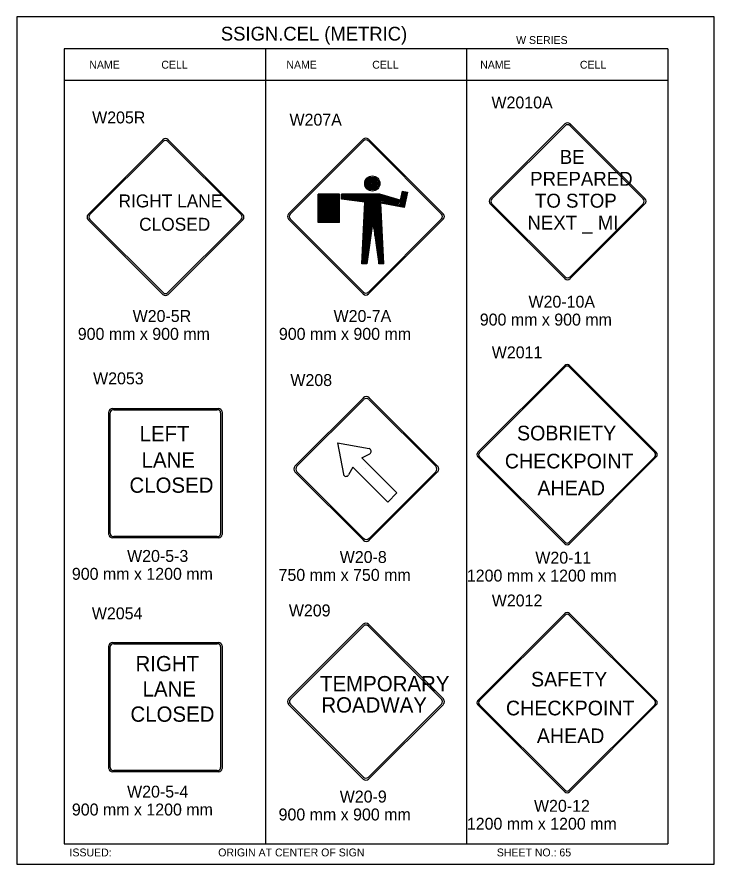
# Model space of a CAD drawing. Extents: x -12 to 6962, y -3756 to 679.
# Drawn here: x 2167.2 to 2342.4, y -696.1 to -483 of the extents above; entities that cross this region are included whole.
import ezdxf

# ---------------------------------------------------------------- set-up
doc = ezdxf.new("R2010")
doc.units = 0
for name, color, linetype in [('Level 1', 7, 'Continuous'), ('Level 2', 7, 'Continuous'), ('Level 3', 7, 'Continuous'), ('Level 62', 7, 'Continuous')]:
    doc.layers.add(name, color=color, linetype=linetype)

msp = doc.modelspace()

# ---------------------------------------------------------------- linework, layer by layer
at = {"layer": 'Level 1'}
for p, q in [((2330.8, -491.06), (2179.04, -491.06)), ((2179.04, -491.06), (2179.04, -691.06)), ((2229.63, -491.06), (2229.63, -691.06)), ((2280.21, -491.17), (2280.21, -691.17)), ((2330.8, -491.06), (2330.8, -691.06)), ((2330.8, -498.98), (2179.04, -498.98)), ((2286.15, -528.71), (2304.93, -509.93)), ((2286.6, -528.77), (2304.99, -510.38)), ((2306.22, -510.38), (2324.61, -528.77)), ((2306.27, -509.93), (2325.05, -528.71)), ((2185.06, -532.69), (2203.84, -513.91)), ((2185.51, -532.74), (2203.9, -514.35)), ((2205.13, -514.35), (2223.52, -532.74)), ((2205.19, -513.91), (2223.97, -532.69)), ((2235.44, -532.55), (2254.22, -513.77)), ((2235.88, -532.61), (2254.28, -514.21)), ((2255.51, -514.21), (2273.9, -532.61)), ((2255.56, -513.77), (2274.35, -532.55)), ((2242.92, -534.68), (2242.92, -527.57)), ((2248.26, -527.57), (2242.92, -527.57)), ((2243.18, -534.68), (2243.18, -527.57)), ((2243.43, -534.68), (2243.43, -527.57)), ((2243.68, -534.68), (2243.68, -527.57)), ((2243.94, -534.68), (2243.94, -527.57)), ((2244.19, -534.68), (2244.19, -527.57)), ((2244.45, -534.68), (2244.45, -527.57)), ((2244.7, -534.68), (2244.7, -527.57)), ((2244.95, -534.68), (2244.95, -527.57)), ((2245.21, -534.68), (2245.21, -527.57)), ((2245.46, -534.68), (2245.46, -527.57)), ((2245.72, -534.68), (2245.72, -527.57)), ((2245.97, -534.68), (2245.97, -527.57)), ((2246.22, -534.68), (2246.22, -527.57)), ((2246.48, -534.68), (2246.48, -527.57)), ((2246.73, -534.68), (2246.73, -527.57)), ((2246.99, -534.68), (2246.99, -527.57)), ((2247.24, -534.68), (2247.24, -527.57)), ((2247.49, -534.68), (2247.49, -527.57)), ((2247.75, -534.68), (2247.75, -527.57)), ((2248, -534.68), (2248, -527.57)), ((2248.26, -534.68), (2248.26, -527.57)), ((2258.42, -527.57), (2248.76, -527.57)), ((2248.76, -528.84), (2248.76, -527.57)), ((2258.42, -527.83), (2248.76, -527.83)), ((2258.42, -528.08), (2248.76, -528.08)), ((2258.42, -528.33), (2248.76, -528.33)), ((2254.67, -529.1), (2248.83, -528.34)), ((2254.7, -528.85), (2248.86, -528.09)), ((2263.28, -529.83), (2258.2, -528.3)), ((2263.35, -529.58), (2258.27, -528.06)), ((2263.42, -529.34), (2258.34, -527.82)), ((2263.5, -529.1), (2258.42, -527.57)), ((2264.11, -526.83), (2263.26, -530.65)), ((2264, -526.81), (2263.5, -529.1)), ((2264.36, -526.89), (2263.51, -530.71)), ((2264.6, -526.94), (2263.76, -530.76)), ((2264, -526.81), (2265.35, -527.11)), ((2264.85, -527), (2264, -530.82)), ((2265.1, -527.05), (2264.25, -530.87)), ((2265.35, -527.11), (2264.5, -530.93)), ((2258.42, -528.59), (2248.76, -528.59)), ((2254.61, -529.6), (2248.76, -528.84)), ((2254.64, -529.35), (2248.8, -528.59)), ((2253.84, -545.1), (2254.61, -529.6)), ((2254.1, -545.11), (2254.86, -529.62)), ((2254.35, -545.12), (2255.11, -529.63)), ((2254.61, -545.14), (2255.37, -529.64)), ((2254.86, -530.11), (2254.86, -528.59)), ((2254.86, -545.15), (2255.62, -529.65)), ((2255.11, -530.11), (2255.11, -528.59)), ((2255.11, -545.16), (2255.87, -529.67)), ((2255.37, -530.11), (2255.37, -528.59)), ((2255.56, -541.28), (2256.13, -529.68)), ((2255.62, -530.11), (2255.62, -528.59)), ((2255.88, -530.11), (2255.88, -528.59)), ((2255.88, -537.99), (2255.88, -530.11)), ((2256.13, -537.99), (2256.13, -528.59)), ((2256.38, -536.46), (2256.38, -528.59)), ((2256.64, -535.45), (2256.64, -528.59)), ((2256.89, -536.21), (2256.89, -528.59)), ((2257.15, -537.99), (2257.15, -528.59)), ((2257.69, -541.03), (2257.15, -529.93)), ((2257.4, -530.11), (2257.4, -528.59)), ((2258.15, -545.16), (2257.4, -529.92)), ((2257.4, -537.99), (2257.4, -530.11)), ((2257.65, -530.11), (2257.65, -528.59)), ((2258.41, -545.15), (2257.66, -529.91)), ((2257.91, -530.11), (2257.91, -528.59)), ((2258.66, -545.14), (2257.91, -529.9)), ((2263.06, -530.56), (2257.98, -529.03)), ((2263.13, -530.31), (2258.05, -528.79)), ((2263.2, -530.07), (2258.12, -528.55)), ((2258.16, -530.11), (2258.16, -528.59)), ((2258.91, -545.12), (2258.16, -529.88)), ((2258.42, -530.11), (2258.42, -528.59)), ((2259.17, -545.11), (2258.42, -529.87)), ((2258.67, -530.11), (2258.67, -528.59)), ((2264.5, -530.93), (2258.67, -529.86)), ((2259.42, -545.1), (2258.67, -529.86)), ((2264.55, -530.68), (2258.72, -529.61)), ((2304.93, -548.83), (2286.15, -530.05)), ((2304.99, -548.38), (2286.6, -530)), ((2305.64, -529.4), (2305.64, -529.4)), ((2324.61, -530), (2306.22, -548.38)), ((2325.05, -530.05), (2306.27, -548.83)), ((2203.84, -552.81), (2185.06, -534.03)), ((2203.9, -552.36), (2185.51, -533.97)), ((2204.5, -533.34), (2204.5, -533.34)), ((2223.52, -533.97), (2205.13, -552.36)), ((2223.97, -534.03), (2205.19, -552.81)), ((2254.22, -552.68), (2235.44, -533.89)), ((2254.28, -552.23), (2235.88, -533.84)), ((2248.26, -534.68), (2242.92, -534.68)), ((2254.95, -533.25), (2254.95, -533.25)), ((2256.63, -534.47), (2255.11, -545.1)), ((2273.9, -533.84), (2255.51, -552.23)), ((2274.35, -533.89), (2255.56, -552.68)), ((2256.63, -534.47), (2258.15, -545.1)), ((2255.88, -537.88), (2254.87, -544.99)), ((2257.38, -537.88), (2258.4, -544.99)), ((2255.11, -545.1), (2253.84, -545.1)), ((2259.42, -545.1), (2258.15, -545.1)), ((2283.06, -592.52), (2304.91, -570.67)), ((2283.44, -592.57), (2304.96, -571.06)), ((2306.01, -571.06), (2327.53, -592.57)), ((2306.06, -570.67), (2327.91, -592.52)), ((2237.06, -595.98), (2254.26, -578.79)), ((2237.56, -596.04), (2254.32, -579.29)), ((2255.69, -579.29), (2272.45, -596.04)), ((2255.75, -578.79), (2272.94, -595.98)), ((2191.21, -581.51), (2217.78, -581.51)), ((2190.26, -613.22), (2190.26, -582.32)), ((2190.62, -612.98), (2190.62, -582.56)), ((2191.49, -581.81), (2217.5, -581.81)), ((2218.37, -582.56), (2218.37, -612.98)), ((2218.73, -582.32), (2218.73, -613.22)), ((2247.79, -590.14), (2249.23, -598.04)), ((2247.79, -590.14), (2255.69, -591.58)), ((2253.9, -593.94), (2255.86, -592.9)), ((2253.9, -593.94), (2262.71, -602.76)), ((2304.91, -615.52), (2283.06, -593.67)), ((2304.96, -615.14), (2283.44, -593.63)), ((2305.49, -593.1), (2305.49, -593.1)), ((2327.53, -593.63), (2306.01, -615.14)), ((2327.91, -593.67), (2306.06, -615.52)), ((2251.6, -596.24), (2250.55, -598.21)), ((2260.41, -605.06), (2251.6, -596.24)), ((2254.77, -596.56), (2254.77, -596.56)), ((2204.48, -597.74), (2204.48, -597.74)), ((2254.26, -614.67), (2237.06, -597.48)), ((2254.32, -614.17), (2237.56, -597.41)), ((2272.45, -597.41), (2255.69, -614.17)), ((2272.94, -597.48), (2255.75, -614.67)), ((2262.71, -602.76), (2260.41, -605.06)), ((2217.78, -614.03), (2191.21, -614.03)), ((2217.5, -613.73), (2191.49, -613.73)), ((2283.06, -654.94), (2304.91, -633.09)), ((2283.44, -654.99), (2304.96, -633.47)), ((2306.01, -633.47), (2327.53, -654.99)), ((2306.06, -633.09), (2327.91, -654.94)), ((2235.45, -654.58), (2254.24, -635.8)), ((2235.9, -654.64), (2254.3, -636.25)), ((2255.53, -636.25), (2273.92, -654.64)), ((2255.58, -635.8), (2274.37, -654.58)), ((2190.26, -672.09), (2190.26, -641.19)), ((2191.21, -640.37), (2217.78, -640.37)), ((2191.49, -640.68), (2217.5, -640.68)), ((2218.73, -641.19), (2218.73, -672.09)), ((2190.62, -671.85), (2190.62, -641.42)), ((2218.37, -641.42), (2218.37, -671.85)), ((2254.24, -674.71), (2235.45, -655.93)), ((2254.3, -674.26), (2235.9, -655.87)), ((2254.81, -655.28), (2254.81, -655.28)), ((2273.92, -655.87), (2255.53, -674.26)), ((2274.37, -655.93), (2255.58, -674.71)), ((2304.91, -677.94), (2283.06, -656.09)), ((2304.96, -677.55), (2283.44, -656.04)), ((2305.49, -655.51), (2305.49, -655.51)), ((2327.53, -656.04), (2306.01, -677.55)), ((2327.91, -656.09), (2306.06, -677.94)), ((2204.4, -656.63), (2204.4, -656.63)), ((2217.78, -672.9), (2191.21, -672.9)), ((2217.5, -672.6), (2191.49, -672.6)), ((2179.04, -691.06), (2330.8, -691.06))]:
    msp.add_line(p, q, dxfattribs=at)
for centre, radius in [((2256.51, -524.91), 1.91), ((2256.49, -524.92), 1.62), ((2256.48, -524.94), 1.38), ((2256.46, -524.95), 1.17), ((2256.45, -524.97), 0.997), ((2256.48, -524.98), 0.847), ((2256.5, -524.98), 0.72), ((2256.52, -524.99), 0.612), ((2256.56, -525), 0.442), ((2256.6, -525.02), 0.204), ((2256.62, -525.03), 0.115)]:
    msp.add_circle(centre, radius, dxfattribs=at)
for centre, radius, start, end in [((2305.6, -510.6), 0.949, 45, 135), ((2305.6, -510.99), 0.87, 45, 135), ((2254.89, -514.44), 0.949, 45, 135), ((2204.52, -514.58), 0.949, 45, 135), ((2204.52, -514.97), 0.87, 45, 135), ((2254.89, -514.83), 0.87, 45, 135), ((2286.82, -529.38), 0.949, 135, 225), ((2287.21, -529.38), 0.87, 135, 225), ((2323.99, -529.38), 0.87, 315, 45), ((2324.38, -529.38), 0.949, 315, 45), ((2185.73, -533.36), 0.949, 135, 225), ((2223.3, -533.36), 0.949, 315, 45), ((2236.11, -533.22), 0.949, 135, 225), ((2236.5, -533.22), 0.87, 135, 225), ((2273.29, -533.22), 0.87, 315, 45), ((2273.68, -533.22), 0.949, 315, 45), ((2186.13, -533.36), 0.87, 135, 225), ((2222.9, -533.36), 0.87, 315, 45), ((2305.6, -548.16), 0.949, 225, 315), ((2305.6, -547.77), 0.87, 225, 315), ((2204.52, -552.14), 0.949, 225, 315), ((2204.52, -551.75), 0.87, 225, 315), ((2254.89, -552.01), 0.949, 225, 315), ((2254.89, -551.62), 0.87, 225, 315), ((2305.49, -571.25), 0.813, 45, 135), ((2305.49, -571.58), 0.745, 45, 135), ((2255, -579.54), 1.06, 45, 135), ((2255, -579.97), 0.969, 45, 135), ((2255.52, -592.27), 0.718, 298.6264, 76.9676), ((2283.64, -593.1), 0.813, 135, 225), ((2283.97, -593.1), 0.745, 135, 225), ((2327, -593.1), 0.745, 315, 45), ((2327.34, -593.1), 0.813, 315, 45), ((2237.81, -596.73), 1.06, 135, 225), ((2238.25, -596.73), 0.969, 135, 225), ((2271.76, -596.73), 0.969, 315, 45), ((2272.2, -596.73), 1.06, 315, 45), ((2249.92, -597.87), 0.712, 192.6656, 332.1451), ((2255, -613.92), 1.06, 225, 315), ((2255, -613.48), 0.969, 225, 315), ((2305.49, -614.95), 0.813, 225, 315), ((2305.49, -614.61), 0.745, 225, 315), ((2305.49, -633.66), 0.813, 45, 135), ((2305.49, -634), 0.745, 45, 135), ((2254.91, -636.47), 0.949, 45, 135), ((2254.91, -636.86), 0.87, 45, 135), ((2236.13, -655.25), 0.949, 135, 225), ((2236.52, -655.25), 0.87, 135, 225), ((2273.3, -655.25), 0.87, 315, 45), ((2273.69, -655.25), 0.949, 315, 45), ((2283.64, -655.51), 0.813, 135, 225), ((2283.97, -655.51), 0.745, 135, 225), ((2327, -655.51), 0.745, 315, 45), ((2327.34, -655.51), 0.813, 315, 45), ((2254.91, -674.04), 0.949, 225, 315), ((2254.91, -673.65), 0.87, 225, 315), ((2305.49, -677.03), 0.745, 225, 315), ((2305.49, -677.36), 0.813, 225, 315)]:
    msp.add_arc(centre, radius, start, end, dxfattribs=at)
for centre, major_axis, start_param, end_param in [((2191.21, -582.32), (-0.949, 0), 4.712389, 6.283185), ((2217.78, -582.32), (0.949, 0), 0, 1.570796), ((2191.49, -582.56), (-0.87, 0), 4.712389, 6.283185), ((2217.5, -582.56), (-0.87, 0), 3.141593, 4.712389), ((2191.21, -613.22), (0.949, 0), 3.141593, 4.712389), ((2191.49, -612.98), (0.87, 0), 3.141593, 4.712389), ((2217.5, -612.98), (0.87, 0), 4.712389, 6.283185), ((2217.78, -613.22), (0.949, 0), 4.712389, 6.283185), ((2191.21, -641.19), (-0.949, 0), 4.712389, 6.283185), ((2191.49, -641.42), (-0.87, 0), 4.712389, 6.283185), ((2217.5, -641.42), (-0.87, 0), 3.141593, 4.712389), ((2217.78, -641.19), (0.949, 0), 0, 1.570796), ((2191.21, -672.09), (0.949, 0), 3.141593, 4.712389), ((2191.49, -671.85), (0.87, 0), 3.141593, 4.712389), ((2217.5, -671.85), (0.87, 0), 4.712389, 6.283185), ((2217.78, -672.09), (0.949, 0), 4.712389, 6.283185)]:
    msp.add_ellipse(centre, major_axis=major_axis, ratio=0.857082, start_param=start_param, end_param=end_param, dxfattribs=at)
at = {"layer": 'Level 62'}
msp.add_lwpolyline([(2167.17, -696.11), (2342.43, -696.11), (2342.43, -483.01), (2167.17, -483.01)], close=True, dxfattribs=at)

# ---------------------------------------------------------------- texts
at = {"layer": 'Level 1'}
for s, height, p in [('BE', 3.5, (2303.64, -519.98)), ('PREPARED', 3.5, (2296.2, -525.48)), ('RIGHT LANE', 3.25, (2192.71, -530.92)), ('TO STOP', 3.5, (2297.41, -530.99)), ('CLOSED', 3.25, (2197.89, -536.79)), ('NEXT _ MI', 3.5, (2295.51, -536.52)), ('LEFT', 3.842, (2197.99, -589.76)), ('SOBRIETY', 3.688, (2292.89, -589.53)), ('LANE', 3.842, (2198.5, -596.36)), ('CHECKPOINT', 3.688, (2289.83, -596.58)), ('CLOSED', 3.842, (2195.45, -602.71)), ('AHEAD', 3.688, (2298.03, -603.35)), ('RIGHT', 3.842, (2196.97, -647.61)), ('SAFETY', 3.688, (2296.41, -651.44)), ('TEMPORARY', 3.842, (2243.36, -652.65)), ('LANE', 3.842, (2198.75, -653.96)), ('ROADWAY', 3.842, (2243.7, -657.99)), ('CHECKPOINT', 3.688, (2290.11, -658.7)), ('CLOSED', 3.842, (2195.7, -660.31)), ('AHEAD', 3.688, (2297.87, -665.69))]:
    msp.add_text(s, height=height, dxfattribs=at).set_placement(p)
at = {"layer": 'Level 2'}
for s, p in [('W2010A', (2286.47, -506.03)), ('W205R', (2186.07, -509.79)), ('W207A', (2235.69, -510.36)), ('W2011', (2286.55, -568.88)), ('W2053', (2186.31, -575.43)), ('W208', (2235.91, -575.86)), ('W2012', (2286.55, -631.3)), ('W2054', (2186, -634.54)), ('W209', (2235.53, -633.81))]:
    msp.add_text(s, height=3, dxfattribs=at).set_placement(p)
at = {"layer": 'Level 3'}
for s, height, p in [('SSIGN.CEL (METRIC)', 3.4642, (2218.43, -488.95)), ('W SERIES', 1.979, (2292.67, -489.82)), ('NAME', 1.98, (2185.36, -496.02)), ('CELL', 1.98, (2203.47, -496.02)), ('NAME', 1.98, (2234.91, -496.02)), ('CELL', 1.98, (2256.49, -496.02)), ('NAME', 1.98, (2283.64, -496.02)), ('CELL', 1.98, (2308.7, -496.02)), ('W20-10A', 3, (2295.78, -556.14)), ('W20-5R', 3, (2196.26, -559.74)), ('W20-7A', 3, (2246.78, -559.74)), ('900 mm x 900 mm', 3, (2283.53, -560.64)), ('900 mm x 900 mm', 3, (2182.46, -564.24)), ('900 mm x 900 mm', 3, (2233.03, -564.24)), ('W20-5-3', 3, (2194.86, -620.1)), ('W20-8', 3, (2248.32, -620.37)), ('W20-11', 3, (2297.5, -620.54)), ('900 mm x 1200 mm', 3, (2180.98, -624.6)), ('750 mm x 750 mm', 3, (2232.94, -624.87)), ('1200 mm x 1200 mm', 3, (2280.28, -625.04)), ('W20-5-4', 3, (2194.86, -679.39)), ('W20-9', 3, (2248.32, -680.63)), ('900 mm x 1200 mm', 3, (2180.98, -683.89)), ('W20-12', 3, (2297.16, -682.96)), ('900 mm x 900 mm', 3, (2232.95, -685.13)), ('1200 mm x 1200 mm', 3, (2280.28, -687.46)), ('ISSUED:', 1.98, (2180.38, -694.18)), ('ORIGIN AT CENTER OF SIGN', 1.9795, (2217.77, -694.18)), ('SHEET NO.: 65', 1.9795, (2287.81, -694.18))]:
    msp.add_text(s, height=height, dxfattribs=at).set_placement(p)

doc.saveas('drawing.dxf')
